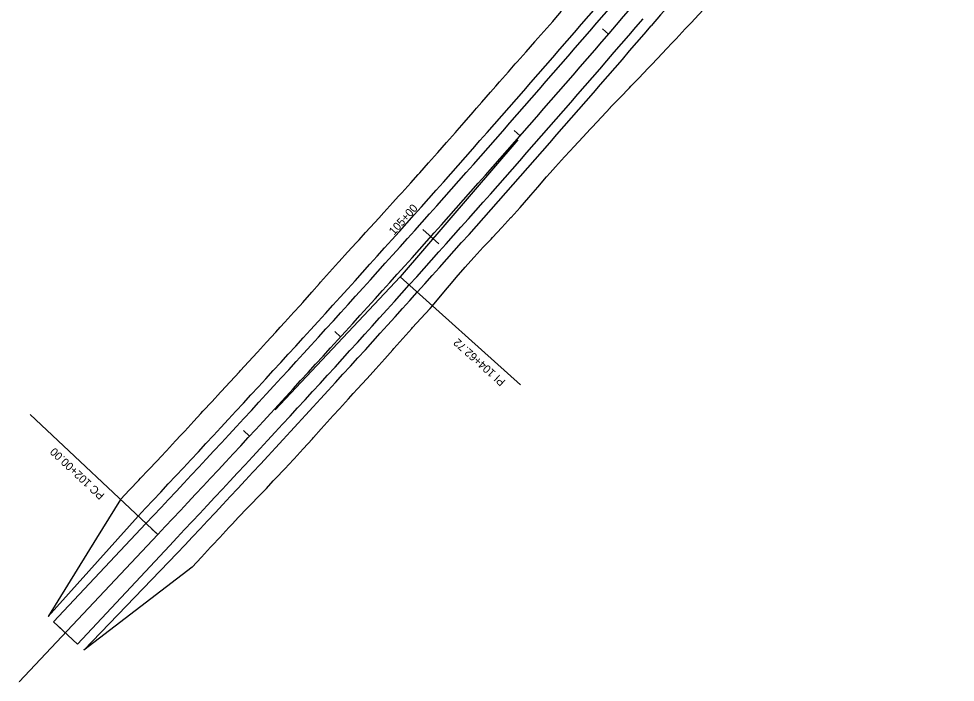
# Model space of a CAD drawing. Extents: x 1375694 to 1433473, y 1931050 to 1967991.
# Drawn here: x 1375694 to 1376389, y 1931050 to 1931542 of the extents above; entities that cross this region are included whole.
import ezdxf

# ---------------------------------------------------------------- set-up
doc = ezdxf.new("R2010")
doc.units = 0
for name, color, linetype in [('R_Horz Alg', 7, 'Continuous'), ('R_Horz Alg Annot', 7, 'Continuous'), ('R_Proposed Const Limits', 7, 'Continuous'), ('R_Proposed Road', 7, 'Continuous')]:
    doc.layers.add(name, color=color, linetype=linetype)

msp = doc.modelspace()

# ---------------------------------------------------------------- linework, layer by layer
at = {"layer": 'R_Horz Alg'}
msp.add_line((1375694.69, 1931050.33), (1375797.48, 1931159.57), dxfattribs=at)
msp.add_arc((1367452.4, 1939012.71), 11459.16, 316.739551, 319.366245, dxfattribs=at)
at = {"layer": 'R_Horz Alg Annot'}
for p in [(1376064.83, 1931452.63), (1375884.66, 1931252.2)]:
    msp.add_line(p, (1375977.53, 1931350.89), dxfattribs=at)
for points in [[(1376127.54, 1931534.97), (1376132.09, 1931531.05)], [(1376061.96, 1931459.55), (1376066.47, 1931455.59)], [(1375994.23, 1931386.04), (1376006.16, 1931375.38)], [(1375977.53, 1931350.89), (1376066.78, 1931270.68)], [(1375928.83, 1931310.44), (1375933.27, 1931306.41)], [(1375797.48, 1931159.57), (1375702.81, 1931248.66)], [(1375861.29, 1931236.76), (1375865.7, 1931232.69)], [(1375793.11, 1931163.68), (1375797.48, 1931159.57)], [(1375724.58, 1931090.86), (1375728.95, 1931086.74)]]:
    msp.add_lwpolyline(points, dxfattribs=at)
at = {"layer": 'R_Proposed Const Limits'}
for p, q in [((1375769.78, 1931185.64), (1375752.13, 1931157.07)), ((1375752.13, 1931157.07), (1375716.13, 1931098.81)), ((1375823.17, 1931135.39), (1375742.76, 1931073.75))]:
    msp.add_line(p, q, dxfattribs=at)
for points in [[(1376029.91, 1931362.85), (1376032.28, 1931365.5), (1376039.09, 1931372.87), (1376044.88, 1931378.91), (1376046.01, 1931380.14), (1376052.81, 1931387.51), (1376059.65, 1931394.86), (1376059.8, 1931395.03), (1376066.36, 1931402.31), (1376072.94, 1931409.89), (1376074.37, 1931411.45), (1376079.52, 1931417.46), (1376086.08, 1931425.05), (1376088.8, 1931428), (1376092.72, 1931432.56), (1376099.5, 1931439.96), (1376103.51, 1931444.31), (1376106.29, 1931447.34), (1376113.12, 1931454.7), (1376118.42, 1931460.43), (1376119.93, 1931462.07), (1376126.74, 1931469.44), (1376133.4, 1931476.51), (1376133.63, 1931476.74), (1376140.62, 1931483.96), (1376147.58, 1931491.21), (1376148.66, 1931492.34), (1376154.57, 1931498.43), (1376161.56, 1931505.65), (1376163.96, 1931508.15), (1376168.46, 1931512.95), (1376175.36, 1931520.25), (1376178.97, 1931524.21), (1376180.79, 1931526.15), (1376182.17, 1931527.58), (1376188.97, 1931534.88), (1376193.79, 1931539.91), (1376195.82, 1931542.13), (1376202.63, 1931549.41)], [(1375769.78, 1931185.64), (1375776.67, 1931192.84), (1375783.53, 1931200.07), (1375784.82, 1931201.44), (1375790.39, 1931207.3), (1375797.27, 1931214.52), (1375799.85, 1931217.26), (1375804.05, 1931221.82), (1375810.81, 1931229.14), (1375814.63, 1931233.31), (1375817.56, 1931236.48), (1375824.29, 1931243.83), (1375829.4, 1931249.37), (1375831.04, 1931251.16), (1375837.8, 1931258.48), (1375844.21, 1931265.38), (1375844.59, 1931265.79), (1375851.36, 1931273.09), (1375858.14, 1931280.4), (1375859.04, 1931281.38), (1375864.9, 1931287.73), (1375871.62, 1931295.09), (1375873.8, 1931297.45), (1375878.35, 1931302.44), (1375885.07, 1931309.8), (1375888.5, 1931313.57), (1375891.77, 1931317.18), (1375898.47, 1931324.56), (1375903.15, 1931329.74), (1375905.14, 1931331.97), (1375911.77, 1931339.41), (1375917.68, 1931346.01), (1375918.42, 1931346.83), (1375925.03, 1931354.29), (1375931.65, 1931361.74), (1375932.17, 1931362.32), (1375938.38, 1931369.09), (1375945.11, 1931376.45), (1375946.9, 1931378.41), (1375951.82, 1931383.81), (1375958.54, 1931391.18), (1375961.6, 1931394.53), (1375965.25, 1931398.55), (1375971.92, 1931405.95), (1375976.22, 1931410.73), (1375978.59, 1931413.36), (1375985.25, 1931420.77), (1375990.8, 1931426.96), (1375991.91, 1931428.19), (1375998.56, 1931435.62), (1376005.21, 1931443.04), (1376005.36, 1931443.21), (1376011.8, 1931450.52), (1376018.37, 1931458.02), (1376019.75, 1931459.6), (1376024.92, 1931465.52), (1376031.48, 1931473.03), (1376034.1, 1931476.04), (1376038.03, 1931480.54), (1376044.57, 1931488.07), (1376048.44, 1931492.48), (1376051.15, 1931495.55), (1376057.75, 1931503.02), (1376062.87, 1931508.85), (1376064.33, 1931510.51), (1376070.91, 1931517.99), (1376077.25, 1931525.25), (1376077.47, 1931525.5), (1376084.06, 1931532.97), (1376090.65, 1931540.46), (1376091.67, 1931541.63), (1376097.22, 1931547.95)], [(1375823.17, 1931135.39), (1375829.96, 1931142.78), (1375836.75, 1931150.17), (1375838.03, 1931151.56), (1375843.52, 1931157.56), (1375850.3, 1931164.96), (1375852.94, 1931167.68), (1375857.27, 1931172.18), (1375864.21, 1931179.41), (1375868.15, 1931183.52), (1375871.16, 1931186.65), (1375878.12, 1931193.88), (1375883.31, 1931199.41), (1375884.98, 1931201.19), (1375891.83, 1931208.52), (1375898.28, 1931215.46), (1375898.66, 1931215.87), (1375905.49, 1931223.21), (1375912.26, 1931230.62), (1375913.15, 1931231.62), (1375918.92, 1931238.12), (1375925.59, 1931245.61), (1375927.78, 1931247.99), (1375932.35, 1931253.03), (1375939.13, 1931260.42), (1375942.57, 1931264.22), (1375945.86, 1931267.86), (1375952.68, 1931275.22), (1375957.44, 1931280.38), (1375959.45, 1931282.61), (1375966.06, 1931290.16), (1375972.03, 1931296.79), (1375972.77, 1931297.61), (1375979.44, 1931305.11), (1375986.05, 1931312.65), (1375986.57, 1931313.24), (1375992.84, 1931320.04), (1375999.74, 1931327.32), (1376001.46, 1931329.38), (1376006.21, 1931335), (1376012.64, 1931342.7), (1376015.57, 1931346.21), (1376019.08, 1931350.4), (1376025.64, 1931357.99), (1376029.91, 1931362.85)]]:
    msp.add_lwpolyline(points, dxfattribs=at)
at = {"layer": 'R_Proposed Road'}
for p, q in [((1375782.92, 1931173.27), (1375716.13, 1931098.81)), ((1375788.74, 1931167.79), (1375720.2, 1931094.98)), ((1375806.22, 1931151.34), (1375737.91, 1931078.32)), ((1375742.76, 1931073.75), (1375812.05, 1931145.86)), ((1375720.2, 1931094.98), (1375737.91, 1931078.32))]:
    msp.add_line(p, q, dxfattribs=at)
for centre, radius, start, end in [((1384844.83, 1924087.81), 11439.16, 137.66069, 139.366245), ((1367452.4, 1939012.71), 11439.16, 316.739551, 319.366245), ((1367452.4, 1939012.71), 11447.16, 316.739551, 319.366245), ((1367452.4, 1939012.71), 11471.16, 316.739551, 319.366245), ((1367452.4, 1939012.71), 11479.16, 316.739551, 319.366245)]:
    msp.add_arc(centre, radius, start, end, dxfattribs=at)

# ---------------------------------------------------------------- texts
at = {"layer": 'R_Horz Alg'}
for p in [(1375797.55, 1931158.91), (1375694.76, 1931049.68)]:
    msp.add_text('+', height=1, rotation=46.73955, dxfattribs=at).set_placement(p)
at = {"layer": 'R_Horz Alg Annot'}
for s, rotation, p in [('105+00', 48.23955, (1375972.9, 1931381.41)), ('PI 104+62.72', 138.0529, (1376056, 1931273.64)), ('PC 102+00.00', 136.73955, (1375758.58, 1931189.31))]:
    msp.add_text(s, height=6, rotation=rotation, dxfattribs=at).set_placement(p)

doc.saveas('drawing.dxf')
